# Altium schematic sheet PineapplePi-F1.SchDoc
size A3
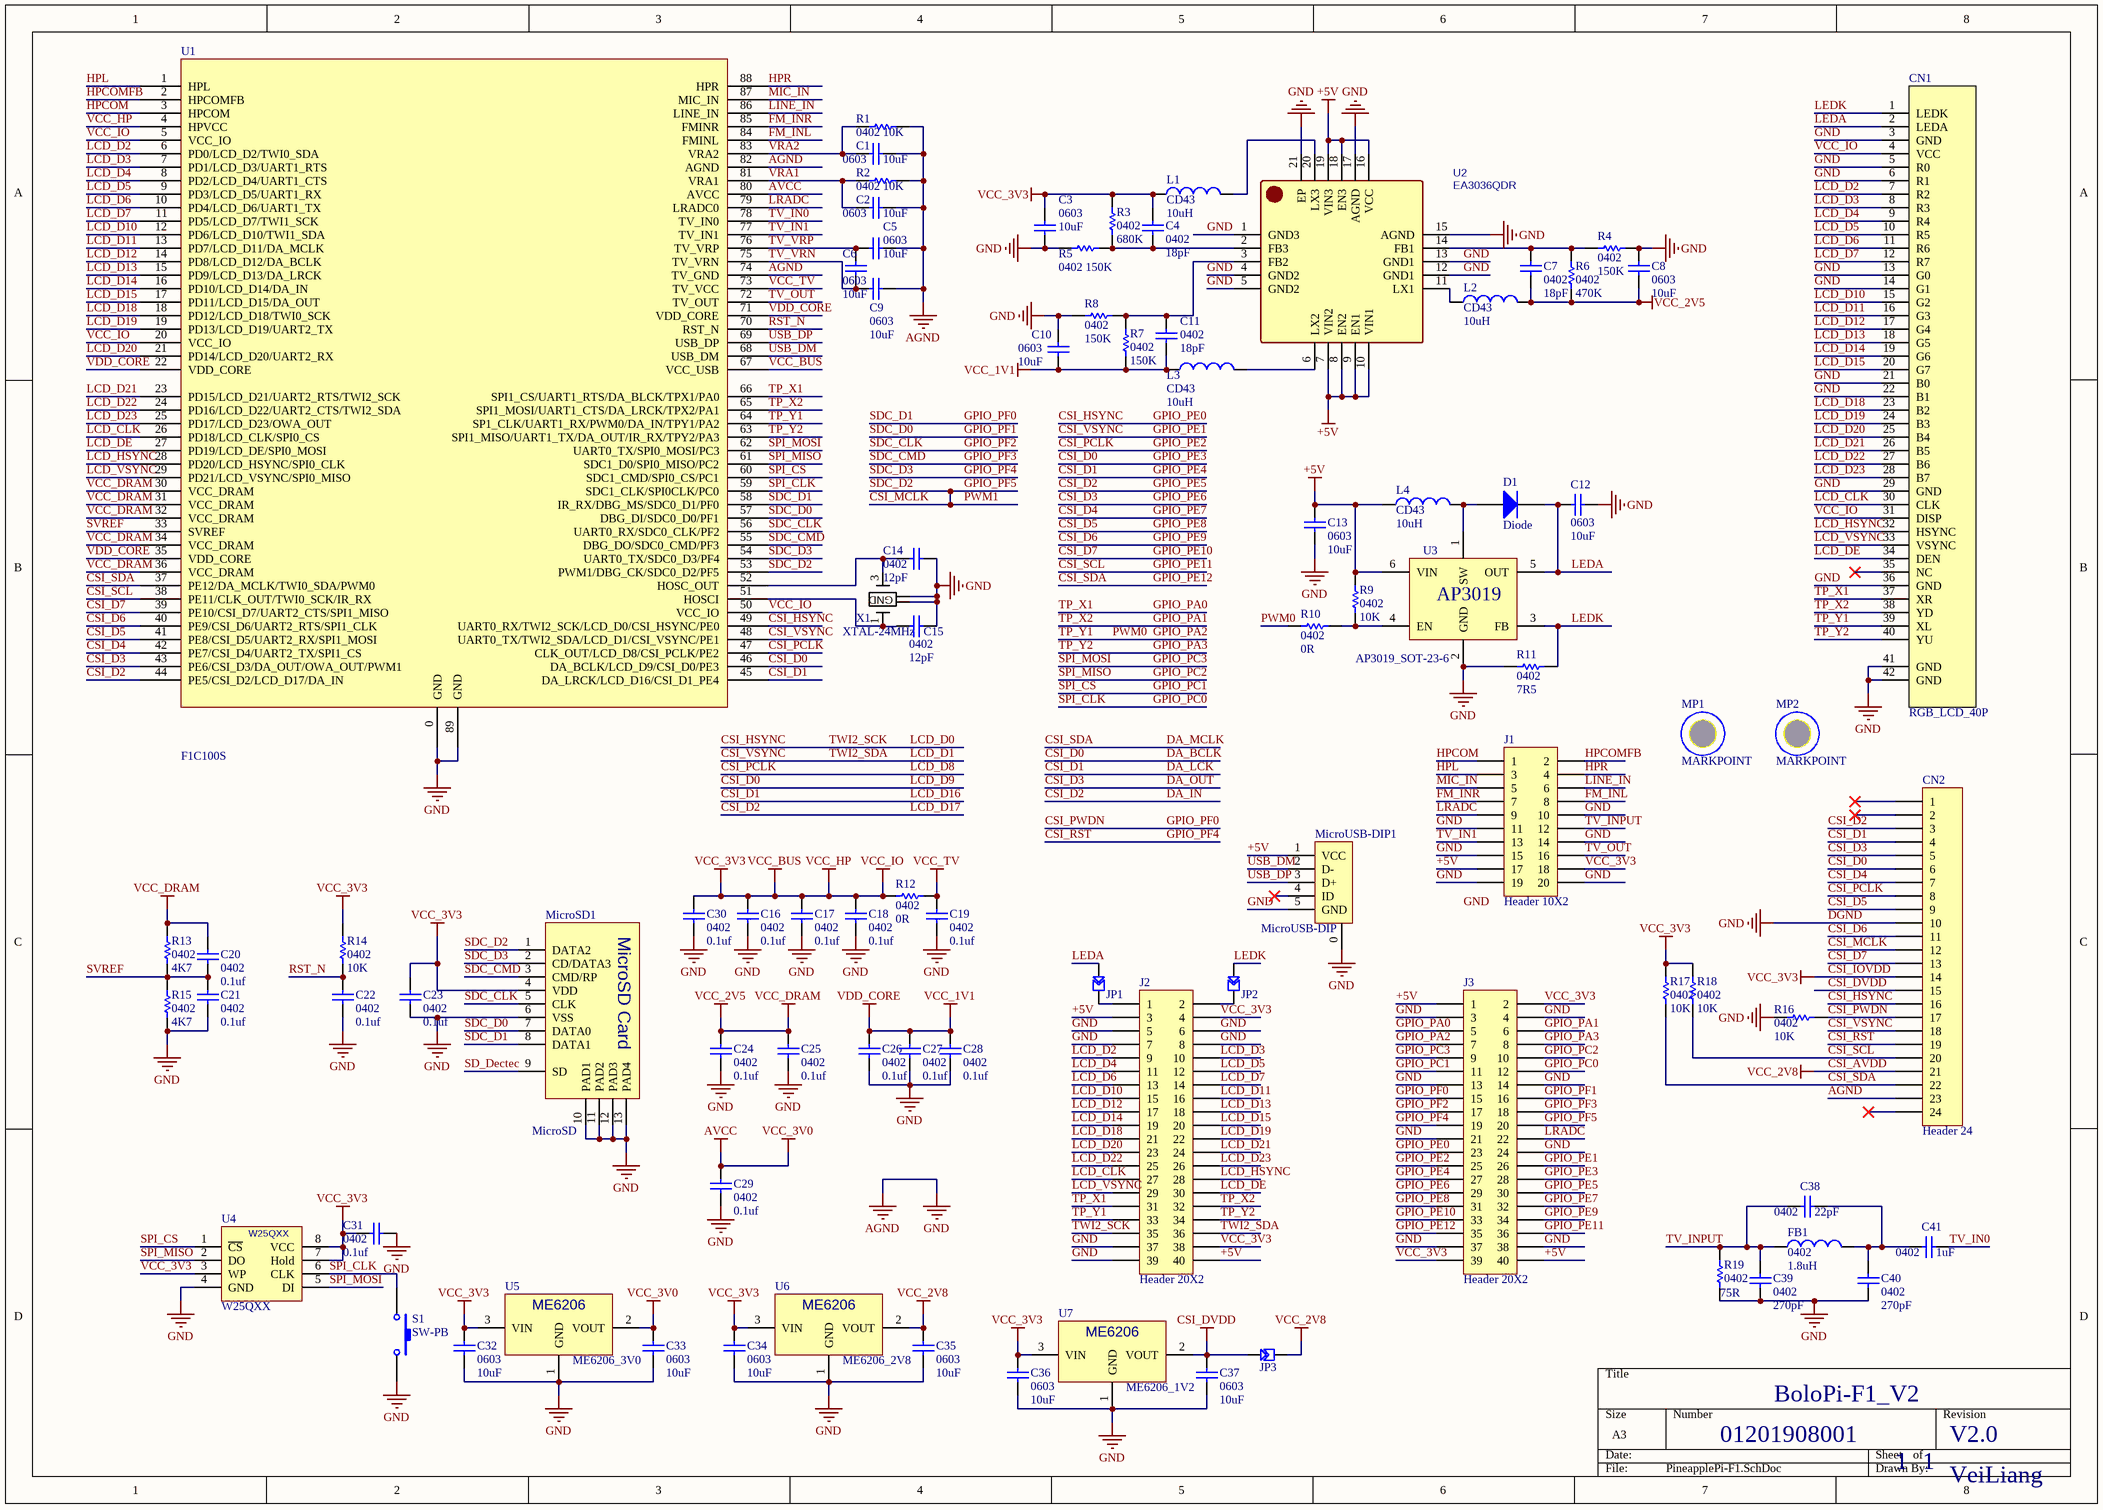
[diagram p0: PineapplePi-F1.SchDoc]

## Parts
C1  0603  value 10uF  [0603AC]
C2  0603  value 10uF  [0603AC]
C3  0603  value 10uF  [0603AC]
C4  0402  value 18pF  [0402AC]
C5  0603  value 10uF  [0603AC]
C6  0603  value 10uF  [0603AC]
C7  0402  value 18pF  [0402AC]
C8  0603  value 10uF  [0603AC]
C9  0603  value 10uF  [0603AC]
C10  0603  value 10uF  [0603AC]
C11  0402  value 18pF  [0402AC]
C12  0603  value 10uF  [0603AC]
C13  0603  value 10uF  [0603AC]
C14  0402  value 12pF  [0402AC]
C15  0402  value 12pF  [0402AC]
C16  0402  value 0.1uf  [0402AC]
C17  0402  value 0.1uf  [0402AC]
C18  0402  value 0.1uf  [0402AC]
C19  0402  value 0.1uf  [0402AC]
C20  0402  value 0.1uf  [0402AC]
C21  0402  value 0.1uf  [0402AC]
C22  0402  value 0.1uf  [0402AC]
C23  0402  value 0.1uf  [0402AC]
C24  0402  value 0.1uf  [0402AC]
C25  0402  value 0.1uf  [0402AC]
C26  0402  value 0.1uf  [0402AC]
C27  0402  value 0.1uf  [0402AC]
C28  0402  value 0.1uf  [0402AC]
C29  0402  value 0.1uf  [0402AC]
C30  0402  value 0.1uf  [0402AC]
C31  0402  value 0.1uf  [0402AC]
C32  0603  value 10uF  [0603AC]
C33  0603  value 10uF  [0603AC]
C34  0603  value 10uF  [0603AC]
C35  0603  value 10uF  [0603AC]
C36  0603  value 10uF  [0603AC]
C37  0603  value 10uF  [0603AC]
C38  0402  value 22pF  [0402AC]
C39  0402  value 270pF  [0402AC]
C40  0402  value 270pF  [0402AC]
C41  0402  value 1uF  [0402AC]
CN1  RGB_LCD_40P  [FH19C-40S-0.5SH]
CN2  Header 24  [FH19C-24S-0.5SH]
D1  Diode  [SOD123]
FB1  0402  value 1.8uH  [0402AR]
J1  Header 10X2  [HDR2X10-2.0mm]
J2  Header 20X2  [HDR2X20]
J3  Header 20X2  [HDR2X20]
JP1  SW-PAD-2  [SW-PAD-2]  (value not drawn)
JP2  SW-PAD-2  [SW-PAD-2]  (value not drawn)
JP3  SW-PAD-2  [SW-PAD-2]  (value not drawn)
L1  CD43  value 10uH  [2520]
L2  CD43  value 10uH  [2520]
L3  CD43  value 10uH  [2520]
L4  CD43  value 10uH  [2520]
MicroSD1  MicroSD  [MicroSD]
MicroUSB-DIP1  MicroUSB-DIP  [MICRO_USB_DIP]
MP1  MARKPOINT  [MARKPOINT]
MP2  MARKPOINT  [MARKPOINT]
R1  0402  value 10K  [0402AR]
R2  0402  value 10K  [0402AR]
R3  0402  value 680K  [0402AR]
R4  0402  value 150K  [0402AR]
R5  0402  value 150K  [0402AR]
R6  0402  value 470K  [0402AR]
R7  0402  value 150K  [0402AR]
R8  0402  value 150K  [0402AR]
R9  0402  value 10K  [0402AR]
R10  0402  value 0R  [0402AR]
R11  0402  value 7R5  [0402AR]
R12  0402  value 0R  [0402AR]
R13  0402  value 4K7  [0402AR]
R14  0402  value 10K  [0402AR]
R15  0402  value 4K7  [0402AR]
R16  0402  value 10K  [0402AR]
R17  0402  value 10K  [0402AR]
R18  0402  value 10K  [0402AR]
R19  0402  value 75R  [0402AR]
S1  SW-PB  [SW-SMD1]
U1  F1C100S  [QFN88-10X10]
U2  EA3036QDR  [QFN20-3x3-0.4]
U3  AP3019_SOT-23-6  [SOT23-6]
U4  W25QXX  [SO-8M]
U5  ME6206_3V0  [SOT-23]
U6  ME6206_2V8  [SOT-23]
U7  ME6206_1V2  [SOT-23]
X1  XTAL-24MHz  [XTAL-3225]

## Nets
+5V: C13.2 J1.17 J2.3 J2.40 J3.1 J3.40 L4.1 MicroUSB-DIP1.1(VCC) R9.1 U2.7(VIN2) U2.8(EN2) U2.9(EN1) U2.10(VIN1) U2.16(VCC) U2.18(EN3) U2.19(VIN3) U3.6(VIN)
AGND: C1.2 C2.2 C3.2 C5.2 C8.2 C9.2 C10.1 C12.2 C13.1 C14.1 C15.1 C16.1 C17.1 C18.1 C19.1 C21.1 C22.1 C23.1 C24.1 C25.1 C26.1 C27.1 C28.1 C29.1 C30.2 C31.1 C32.1 C33.1 C34.1 C35.1 C36.1 C37.1 C39.2 C40.2 CN1.3(GND) CN1.5(R0) CN1.6(R1) CN1.13(G0) CN1.14(G1) CN1.21(B0) CN1.22(B1) CN1.29(GND) CN1.36(GND) CN1.41(GND) CN1.42(GND) CN2.10 CN2.23 J1.10 J1.11 J1.14 J1.15 J1.19 J1.20 J2.5 J2.6 J2.7 J2.8 J2.37 J2.39 J3.3 J3.4 J3.13 J3.14 J3.21 J3.24 J3.37 J3.38 MicroSD1.6(VSS) MicroSD1.10(PAD1) MicroSD1.11(PAD2) MicroSD1.12(PAD3) MicroSD1.13(PAD4) MicroUSB-DIP1.0 MicroUSB-DIP1.5(GND) R1.1 R2.1 R4.2 R5.2 R8.2 R11.1 R15.1 R16.1 R19.1 S1.2 U1.0(GND) U1.74(TV_GND) U1.82(AGND) U1.89(GND) U2.1(GND3) U2.4(GND2) U2.5(GND2) U2.12(GND1) U2.13(GND1) U2.15(AGND) U2.17(AGND) U2.21(EP) U3.2(GND) U4.4(GND) U5.1(GND) U6.1(GND) U7.1(GND) X1.2 X1.4  [also labelled DGND, GND]
AVCC: C29.2 C33.2 U1.80(AVCC) U5.2(VOUT)  [also labelled VCC_3V0]
CSI_AVDD: C35.2 CN2.21 JP3.2 U6.2(VOUT)  [also labelled VCC_2V8]
CSI_DVDD: C37.2 CN2.15 JP3.1 U7.2(VOUT)
CSI_IOVDD: C3.1 C4.1 C16.2 C17.2 C18.2 C23.2 C30.1 C31.2 C32.2 C34.2 C36.2 CN1.4(VCC) CN1.31(DISP) CN2.14 J1.18 J2.4 J2.38 J3.2 J3.39 L1.1 MicroSD1.4(VDD) R3.2 R12.2 R14.2 R17.2 R18.2 U1.4(HPVCC) U1.5(VCC_IO) U1.20(VCC_IO) U1.50(VCC_IO) U1.67(VCC_USB) U4.3(WP) U4.7(Hold) U4.8(VCC) U5.3(VIN) U6.3(VIN) U7.3(VIN)  [also labelled VCC_3V3, VCC_BUS, VCC_HP, VCC_IO]
VCC_DRAM: C7.1 C8.1 C20.2 C24.2 C25.2 L2.2 R6.2 R13.2 U1.30(VCC_DRAM) U1.31(VCC_DRAM) U1.32(VCC_DRAM) U1.34(VCC_DRAM) U1.36(VCC_DRAM)  [also labelled VCC_2V5]
VCC_TV: C19.2 R12.1 U1.73(TV_VCC)
VDD_CORE: C10.2 C11.1 C26.2 C27.2 C28.2 L3.1 R7.1 U1.22(VDD_CORE) U1.35(VDD_CORE) U1.71(VDD_CORE)  [also labelled VCC_1V1]
CSI_D0: CN2.6 J3.28 U1.46(DA_BCLK/LCD_D9/CSI_D0/PE3)  [also labelled DA_BCLK, GPIO_PE3, LCD_D9]
CSI_D1: CN2.4 J3.27 U1.45(DA_LRCK/LCD_D16/CSI_D1_PE4)  [also labelled DA_LCK, GPIO_PE4, LCD_D16]
CSI_D2: CN2.3 J3.30 U1.44(PE5/CSI_D2/LCD_D17/DA_IN)  [also labelled DA_IN, GPIO_PE5, LCD_D17]
CSI_D3: CN2.5 J3.29 U1.43(PE6/CSI_D3/DA_OUT/OWA_OUT/PWM1)  [also labelled DA_OUT, GPIO_PE6]
CSI_D4: CN2.7 J3.32 U1.42(PE7/CSI_D4/UART2_TX/SPI1_CS)  [also labelled GPIO_PE7]
CSI_D5: CN2.9 J3.31 U1.41(PE8/CSI_D5/UART2_RX/SPI1_MOSI)  [also labelled GPIO_PE8]
CSI_D6: CN2.11 J3.34 U1.40(PE9/CSI_D6/UART2_RTS/SPI1_CLK)  [also labelled GPIO_PE9]
CSI_D7: CN2.13 J3.33 U1.39(PE10/CSI_D7/UART2_CTS/SPI1_MISO)  [also labelled GPIO_PE10]
CSI_HSYNC: CN2.16 J2.35 J3.23 U1.49(UART0_RX/TWI2_SCK/LCD_D0/CSI_HSYNC/PE0)  [also labelled GPIO_PE0, LCD_D0, TWI2_SCK]
CSI_MCLK: CN2.12 J3.20 MicroSD1.1(DATA2) U1.53(PWM1/DBG_CK/SDC0_D2/PF5)  [also labelled GPIO_PF5, PWM1, SDC_D2]
CSI_PCLK: CN2.8 J3.25 U1.47(CLK_OUT/LCD_D8/CSI_PCLK/PE2)  [also labelled GPIO_PE2, LCD_D8]
CSI_PWDN: CN2.17 J3.15 MicroSD1.8(DATA1) R16.2 U1.58(IR_RX/DBG_MS/SDC0_D1/PF0)  [also labelled GPIO_PF0, SDC_D1]
CSI_RST: CN2.19 J3.19 MicroSD1.2(CD/DATA3) U1.54(UART0_TX/SDC0_D3/PF4)  [also labelled GPIO_PF4, SDC_D3]
CSI_SCL: CN2.20 J3.36 R18.1 U1.38(PE11/CLK_OUT/TWI0_SCK/IR_RX)  [also labelled GPIO_PE11]
CSI_SDA: CN2.22 J3.35 R17.1 U1.37(PE12/DA_MCLK/TWI0_SDA/PWM0)  [also labelled DA_MCLK, GPIO_PE12]
CSI_VSYNC: CN2.18 J2.36 J3.26 U1.48(UART0_TX/TWI2_SDA/LCD_D1/CSI_VSYNC/PE1)  [also labelled GPIO_PE1, LCD_D1, TWI2_SDA]
FM_INL: J1.8 U1.84(FMINL)
FM_INR: J1.7 U1.85(FMINR)
GPIO_PA0: CN1.37(XR) J2.31 J3.5 U1.66(SPI1_CS/UART1_RTS/DA_BLCK/TPX1/PA0)  [also labelled TP_X1]
GPIO_PA1: CN1.38(YD) J2.32 J3.6 U1.65(SPI1_MOSI/UART1_CTS/DA_LRCK/TPX2/PA1)  [also labelled TP_X2]
GPIO_PA2: CN1.39(XL) J2.33 J3.7 R10.1 U1.64(SP1_CLK/UART1_RX/PWM0/DA_IN/TPY1/PA2)  [also labelled PWM0, TP_Y1]
GPIO_PA3: CN1.40(YU) J2.34 J3.8 U1.63(SPI1_MISO/UART1_TX/DA_OUT/IR_RX/TPY2/PA3)  [also labelled TP_Y2]
GPIO_PC0: J3.12 S1.1 U1.59(SDC1_CLK/SPI0CLK/PC0) U4.6(CLK)  [also labelled SPI_CLK]
GPIO_PC1: J3.11 U1.60(SDC1_CMD/SPI0_CS/PC1) U4.1(~{CS})  [also labelled SPI_CS]
GPIO_PC2: J3.10 U1.61(SDC1_D0/SPI0_MISO/PC2) U4.2(DO)  [also labelled SPI_MISO]
GPIO_PC3: J3.9 U1.62(UART0_TX/SPI0_MOSI/PC3) U4.5(DI)  [also labelled SPI_MOSI]
GPIO_PF1: J3.16 MicroSD1.7(DATA0) U1.57(DBG_DI/SDC0_D0/PF1)  [also labelled SDC_D0]
GPIO_PF2: J3.17 MicroSD1.5(CLK) U1.56(UART0_RX/SDC0_CLK/PF2)  [also labelled SDC_CLK]
GPIO_PF3: J3.18 MicroSD1.3(CMD/RP) U1.55(DBG_DO/SDC0_CMD/PF3)  [also labelled SDC_CMD]
HPCOM: J1.1 U1.3(HPCOM)
HPCOMFB: J1.2 U1.2(HPCOMFB)
HPL: J1.3 U1.1(HPL)
HPR: J1.4 U1.88(HPR)
LCD_CLK: CN1.30(CLK) J2.27 U1.26(PD18/LCD_CLK/SPI0_CS)
LCD_D2: CN1.7(R2) J2.9 U1.6(PD0/LCD_D2/TWI0_SDA)
LCD_D3: CN1.8(R3) J2.10 U1.7(PD1/LCD_D3/UART1_RTS)
LCD_D4: CN1.9(R4) J2.11 U1.8(PD2/LCD_D4/UART1_CTS)
LCD_D5: CN1.10(R5) J2.12 U1.9(PD3/LCD_D5/UART1_RX)
LCD_D6: CN1.11(R6) J2.13 U1.10(PD4/LCD_D6/UART1_TX)
LCD_D7: CN1.12(R7) J2.14 U1.11(PD5/LCD_D7/TWI1_SCK)
LCD_D10: CN1.15(G2) J2.15 U1.12(PD6/LCD_D10/TWI1_SDA)
LCD_D11: CN1.16(G3) J2.16 U1.13(PD7/LCD_D11/DA_MCLK)
LCD_D12: CN1.17(G4) J2.17 U1.14(PD8/LCD_D12/DA_BCLK)
LCD_D13: CN1.18(G5) J2.18 U1.15(PD9/LCD_D13/DA_LRCK)
LCD_D14: CN1.19(G6) J2.19 U1.16(PD10/LCD_D14/DA_IN)
LCD_D15: CN1.20(G7) J2.20 U1.17(PD11/LCD_D15/DA_OUT)
LCD_D18: CN1.23(B2) J2.21 U1.18(PD12/LCD_D18/TWI0_SCK)
LCD_D19: CN1.24(B3) J2.22 U1.19(PD13/LCD_D19/UART2_TX)
LCD_D20: CN1.25(B4) J2.23 U1.21(PD14/LCD_D20/UART2_RX)
LCD_D21: CN1.26(B5) J2.24 U1.23(PD15/LCD_D21/UART2_RTS/TWI2_SCK)
LCD_D22: CN1.27(B6) J2.25 U1.24(PD16/LCD_D22/UART2_CTS/TWI2_SDA)
LCD_D23: CN1.28(B7) J2.26 U1.25(PD17/LCD_D23/OWA_OUT)
LCD_DE: CN1.34(DEN) J2.30 U1.27(PD19/LCD_DE/SPI0_MOSI)
LCD_HSYNC: CN1.32(HSYNC) J2.28 U1.28(PD20/LCD_HSYNC/SPI0_CLK)
LCD_VSYNC: CN1.33(VSYNC) J2.29 U1.29(PD21/LCD_VSYNC/SPI0_MISO)
LEDA: C12.1 CN1.2(LEDA) D1.2(K) JP1.1 U3.5(OUT)
LEDK: CN1.1(LEDK) JP2.1 R11.2 U3.3(FB)
LINE_IN: J1.6 U1.86(LINE_IN)
LRADC: J1.9 J3.22 U1.79(LRADC0)
MIC_IN: J1.5 U1.87(MIC_IN)
RST_N: C22.2 R14.1 U1.70(RST_N)
SD_Dectec: MicroSD1.9(SD)
SVREF: C20.1 C21.2 R13.1 R15.2 U1.33(SVREF)
TV_IN0: C41.1 U1.78(TV_IN0)
TV_IN1: J1.13 U1.77(TV_IN1)
TV_INPUT: C38.2 C39.1 FB1.1 J1.12 R19.2
TV_OUT: J1.16 U1.72(TV_OUT)
TV_VRN: C6.1 C9.1 U1.75(TV_VRN)
TV_VRP: C5.1 C6.2 U1.76(TV_VRP)
USB_DM: MicroUSB-DIP1.2(D-) U1.68(USB_DM)
USB_DP: MicroUSB-DIP1.3(D+) U1.69(USB_DP)
VRA1: C2.1 R2.2 U1.81(VRA1)
VRA2: C1.1 R1.2 U1.83(VRA2)
NetC4_2: C4.2 R3.1 R5.1 U2.2(FB3)
NetC7_2: C7.2 R4.1 R6.1 U2.14(FB1)
NetC11_2: C11.2 R7.2 R8.1 U2.3(FB2)
NetC14_2: C14.2 U1.52(HOSC_OUT) X1.3(GND)
NetC15_2: C15.2 U1.51(HOSCI) X1.1
NetC38_1: C38.1 C40.1 C41.2 FB1.2
NetD1_1: D1.1(A) L4.2 U3.1(SW)
NetJ2_1: J2.1 JP1.2
NetJ2_2: J2.2 JP2.2
NetL1_2: L1.2 U2.20(LX3)
NetL2_1: L2.1 U2.11(LX1)
NetL3_2: L3.2 U2.6(LX2)
NetR9_2: R9.2 R10.2 U3.4(EN)

Not connected (* = marked no-connect by the designer): CN1 35(NC)*; CN2 1* 2* 24*; MicroUSB-DIP1 4(ID)*

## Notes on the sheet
- 01201908001
- BoloPi-F1_V2
- V2.0
- 1
- VeiLiang
- Labels drawn without touching a wire or pin: GND

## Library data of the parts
C1-C41 = Cap: Capacitor
CN2 = Header 24: Header, 24-Pin
D1 = Diode: Default Diode
FB1 = Inductor: CD43; Code_IEC: 1005
J1 = Header 10X2: Header, 10-Pin, Dual row
J2 J3 = Header 20X2: Header, 20-Pin, Dual row
L1-L4 = Inductor: Code_IEC: 1005
R1 R2 R4 R5 R19 = Res1: Resistor
R3 R6-R18 = Res1
S1 = SW-PB: Switch
U2 = EA3036QDR: BOM_Manufacturer: Everanalog
U3 = AP3019
U5-U7 = ME6206
X1 = XTAL-SMD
